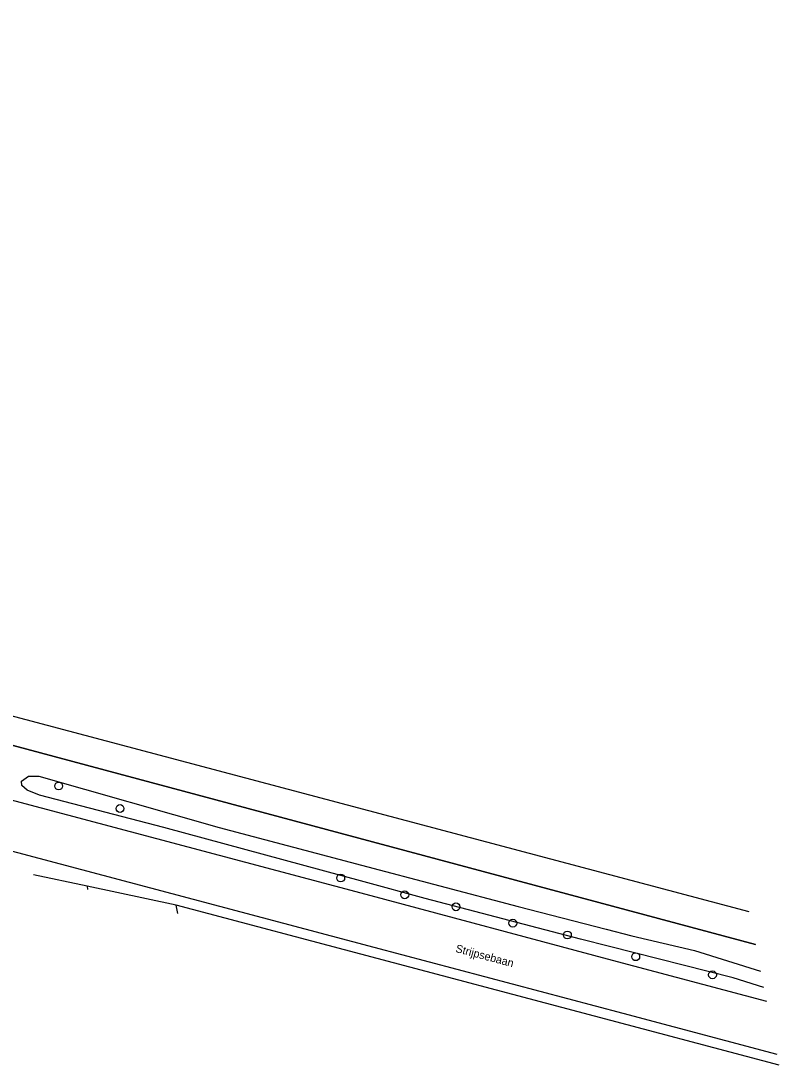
# Model space of a CAD drawing. Extents: x 152881 to 155736, y 382924 to 386919.
# Drawn here: x 154344 to 154438.6, y 383057.4 to 383187.8 of the extents above; entities that cross this region are included whole.
import ezdxf

# ---------------------------------------------------------------- set-up
doc = ezdxf.new("R2010")
doc.units = 0
for name, color, linetype in [('IMGEO_Boom', 7, 'Continuous'), ('IMGEO_Bouwland', 7, 'Continuous'), ('IMGEO_Groenvoorziening', 7, 'Continuous'), ('IMGEO_Hek', 7, 'Continuous'), ('IMGEO_Loofbos', 7, 'Continuous'), ('IMGEO_Openbare_ruimte_label', 7, 'Continuous'), ('IMGEO_Rijbaan_lokaal_gesloten', 7, 'Continuous'), ('IMGEO_Waterloop', 7, 'Continuous')]:
    doc.layers.add(name, color=color, linetype=linetype)

msp = doc.modelspace()

# ---------------------------------------------------------------- linework, layer by layer
at = {"layer": 'IMGEO_Boom'}
for centre in [(154348.72, 383092.28), (154356.37, 383089.47), (154383.92, 383080.79), (154391.91, 383078.7), (154398.3, 383077.2), (154405.4, 383075.16), (154412.21, 383073.67), (154420.74, 383070.96), (154430.32, 383068.7)]:
    msp.add_circle(centre, 0.489, dxfattribs=at)
at = {"layer": 'IMGEO_Bouwland'}
for points in [[(154438.63, 383057.42), (154363.39, 383077.4)], [(154363.6, 383076.35), (154363.39, 383077.4)]]:
    msp.add_lwpolyline(points, dxfattribs=at)
at = {"layer": 'IMGEO_Groenvoorziening'}
for points in [[(154435.67, 383072.5), (154310.72, 383105.99), (154303.19, 383113.54), (154303.01, 383113.96)], [(154352.25, 383079.76), (154345.58, 383081.17)], [(154352.25, 383079.76), (154352.32, 383079.34)], [(154363.39, 383077.4), (154352.25, 383079.76)]]:
    msp.add_lwpolyline(points, dxfattribs=at)
at = {"layer": 'IMGEO_Hek'}
msp.add_lwpolyline([(154300.15, 383120.57), (154303.01, 383113.96), (154303.19, 383113.54), (154310.72, 383105.99), (154435.67, 383072.5)], dxfattribs=at)
at = {"layer": 'IMGEO_Loofbos'}
msp.add_lwpolyline([(154318.87, 383187.85), (154329.58, 383138.09), (154324.88, 383137.08), (154331.37, 383106.91), (154337.23, 383102.55), (154434.86, 383076.6)], dxfattribs=at)
at = {"layer": 'IMGEO_Rijbaan_lokaal_gesloten'}
for points in [[(154305.23, 383109.04), (154307.14, 383106.79), (154307.45, 383106.42), (154309.86, 383103.97), (154312.11, 383102.09), (154312.58, 383101.77), (154314.52, 383100.42), (154317.07, 383098.98), (154319.74, 383097.77), (154322.13, 383096.91), (154330.15, 383094.13), (154342.6, 383090.6), (154387.06, 383078.76), (154417.81, 383070.55), (154437.06, 383065.42)], [(154305.09, 383092.26), (154305.28, 383092.42), (154305.59, 383092.66), (154305.93, 383092.86), (154306.28, 383093.03), (154306.64, 383093.17), (154307.02, 383093.28), (154309.74, 383093.01), (154325.87, 383088.7), (154334.91, 383086.27), (154388.05, 383072.17), (154419.14, 383063.91), (154438.36, 383058.8)]]:
    msp.add_lwpolyline(points, dxfattribs=at)
at = {"layer": 'IMGEO_Waterloop'}
for points in [[(154436.72, 383067.13), (154432.91, 383068.34), (154417.48, 383072.23), (154413.83, 383073.15), (154394.46, 383078.23), (154386.83, 383080.31), (154361.84, 383087.11), (154346.33, 383091.14), (154344.78, 383091.76), (154344.11, 383092.33), (154344.08, 383092.89), (154344.95, 383093.51), (154346.22, 383093.53)], [(154346.22, 383093.53), (154368.73, 383087.1), (154386.51, 383082.4), (154406.06, 383077.23), (154417.05, 383074.4), (154420.24, 383073.57), (154428.08, 383071.74), (154436.32, 383069.17)]]:
    msp.add_lwpolyline(points, dxfattribs=at)

# ---------------------------------------------------------------- texts
at = {"layer": 'IMGEO_Openbare_ruimte_label'}
msp.add_text('Strijpsebaan', height=1, rotation=345.1018, dxfattribs=at).set_placement((154398.18, 383071.56))

doc.saveas('drawing.dxf')
